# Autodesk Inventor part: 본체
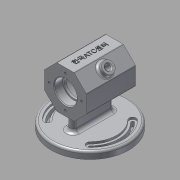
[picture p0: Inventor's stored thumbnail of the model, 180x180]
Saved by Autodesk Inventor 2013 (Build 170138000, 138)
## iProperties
Created: 2017-06
Part Number: 본체
Material: 알루미늄 6061
Document SubType Name: Modeling
Designer: Administrator
Density: 2.71 g/cm^3
Mass: 656.312 g
Surface Area: 514.605 cm^2
Volume: 242.182 cm^3
Author: Administrator
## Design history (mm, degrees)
sketch "스케치2"
  geometry: L1 (0, 0)-(70, 0); L2 (0, 17)-(0, 30); L3 (0, 30)-(70, 30); L4 (70, 17)-(70, 30); L5 (1, 16)-(11.7, 16); L6 (12, 15.7)-(12, 14); L7 (12, 14)-(15, 14); L8 (15, 14)-(15, 22); L9 (18, 25)-(52, 25); L10 (55, 22)-(55, 14); L11 (55, 14)-(58, 14); L12 (58, 14)-(58, 15.7); L13 (58.3, 16)-(69, 16); L14 (0, 17)-(1, 16); L15 (70, 17)-(69, 16); A1 r 3 centre (52, 22) between (55, 22) and (52, 25); A2 r 3 centre (18, 22) between (18, 25) and (15, 22); A3 r 0.3 centre (58.3, 15.7) between (58.3, 16) and (58, 15.7); A4 r 0.3 centre (11.7, 15.7) between (12, 15.7) and (11.7, 16); 8 further points
  constraints: 30 end point, 14 point on line, 8 point on circle, 8 tangent, 6 parallel, 6 perpendicular, 4 centre point, 1 collinear, 1 equal radius, 1 horizontal
  dimensions: "d0" = 70 distance of L1.start L1.end; "d1" = 60 diameter of L3 L1; "d2" = 32 diameter of L5 L1; "d3" = 28 diameter of L7 L1; "d4" = 12 distance from line of point (0, 16) L6; "d5" = 12 distance of point (70, 16) point (58, 16); "d6" = 32 diameter of L13 L1; "d7" = 28 diameter of L11 L1; "d9" = 40 distance between parallel lines of L10 L8; "d10" = 3 radius of A1; "d11" = 1 distance of L2.start point (0, 16); "d12" = 1 distance of L5.start point (0, 16) (= d11); "d13" = 1 distance of L4.start point (70, 16) (= d11); "d14" = 1 distance of L13.end point (70, 16) (= d13); "d15" = 0.3 distance of point (58.3, 16) point (58, 16); "d16" = 0.3 distance of point (58, 15.7) point (58, 16) (= d15); "d17" = 0.3 distance of point (11.7, 16) point (12, 16) (= d15); "d18" = 0.3 distance of point (12, 15.7) point (12, 16) (= d17); "d148" = 50 diameter of L9 L1; "d160" = 0.3 radius of A3; "d161" = 0.3 radius of A4
revolve "회전1" sketch "스케치2" stored, may be unused: angle "d19" = 90 deg
sketch "스케치7"
  geometry: L1 (0, 0)-(0, 30); L2 (0, 30)-(12.426, 30); L3 (6.506, 15.706)-(12.426, 30); L4 (-6.506, 15.706)-(-12.426, 30); L5 (0, 30)-(-12.426, 30); A1 r 17 centre (0, 0) between (-7.11, 15.442) and (10.381, 13.462) reference; A2 r 17 centre (0, 0) between (10.381, 13.462) and (-7.11, 15.442); A3 r 17 centre (0, 0) between (6.506, 15.706) and (-6.506, 15.706); 1 further point
  constraints: 10 end point, 7 point on circle, 2 centre point, 2 symmetric about line, 1 horizontal, 1 perpendicular, 1 vertical, 1 vertical alignment, 1 other
  dimensions: "d43" = 22.5 deg angle of L3 L1
extrude "돌출3" join sketch "스케치7" distance "d44" = 70; taper "d45" = 0 deg
node "작업 평면1"
sketch "스케치8"
  geometry: C1 r 55 at (0, 35); 1 further point
  constraints: 1 centre point
  dimensions: "d50" = 0 horizontal distance of point (0, 0) C1.centre; "d51" = 35 distance of C1.centre point (0, 0); "d52" = 110 diameter of C1
extrude "돌출4" join sketch "스케치8" distance "d53" = 10; taper "d54" = 0 deg
sketch "스케치9"
  geometry: L1 (0, -24)-(0, 24); L2 (-5, -24)-(-5, 24); L3 (4.951, 24.701)-(4.951, -24.701); C1 r 55 at (0, 0) reference; A1 r 5 centre (0, -24) between (-5, -24) and (4.951, -24.701); A2 r 5 centre (0, 24) between (-5, 24) and (4.951, 24.701); 1 further point
  constraints: 6 end point, 4 point on circle, 2 centre point, 2 coincident, 1 equal radius, 1 parallel, 1 tangent, 1 vertical
  dimensions: "d56" = 0 distance from line of C1.centre L1; "d57" = 48 distance of L1.start L1.end; "d58" = 24 distance of L1.start C1.centre; "d59" = 10 diameter of A1
extrude "돌출5" join sketch "스케치9" stored distance "d60" = 10; taper "d61" = 0 deg
sketch "스케치10"
  geometry: L1 (-5, -24)-(-5, 24) reference; L2 (4.951, 24.701)-(4.951, -24.701) reference; L3 (0, 0)-(-48, 0); L4 (0, 0)-(48, 0); L5 (0, -24)-(0, 24); L6 (0, 0)-(-5, -5); L7 (-26.87, -26.87)-(-33.941, -33.941); L8 (0, 0)-(-5, 5); L9 (-26.87, 26.87)-(-33.941, 33.941); L10 (0, 0)-(4.951, -4.951); L11 (26.87, -26.87)-(33.941, -33.941); L12 (0, 0)-(4.951, 4.951); L13 (26.87, 26.87)-(33.941, 33.941); C1 r 55 at (0, 0) reference; A1 r 5 centre (0, 24) between (4.951, 24.701) and (-5, 24) reference; A2 r 5 centre (0, -24) between (-5, -24) and (4.951, -24.701) reference; A3 r 5 centre (-30.406, -30.406) between (-33.941, -33.941) and (-26.67, -33.73); A4 r 5 centre (-30.406, 30.406) between (-26.87, 26.87) and (-26.67, 33.73); A5 r 5 centre (30.406, -30.406) between (33.941, -33.941) and (26.67, -33.73); A6 r 5 centre (30.406, 30.406) between (26.87, 26.87) and (26.67, 33.73); A7 r 38 centre (0, 0) between (26.87, -26.87) and (26.87, 26.87); A8 r 38 centre (0, 0) between (-26.87, 26.87) and (-26.87, -26.87); A9 r 43 centre (0, 0) between (26.67, -33.73) and (26.67, 33.73); A10 r 43 centre (0, 0) between (-26.67, 33.73) and (-26.67, -33.73); A11 r 48 centre (0, 0) between (33.941, -33.941) and (33.941, 33.941); A12 r 48 centre (0, 0) between (-33.941, 33.941) and (-33.941, -33.941); 1 further point
  constraints: 30 point on circle, 22 end point, 10 centre point, 4 midpoint, 4 point on line, 3 coincident, 3 symmetric about line, 2 perpendicular, 1 collinear
  dimensions: "d67" = 45 deg angle of L3 L7
extrude "돌출6" cut sketch "스케치10" distance "d68" = 3; taper "d69" = 0 deg
node "작업 평면2"
sketch "스케치11"
  geometry: C1 r 8 at (12.426, 35); 1 further point
  constraints: 1 centre point
  dimensions: "d71" = 0 horizontal distance of point (12.426, 0) C1.centre; "d72" = 35 distance of point (12.426, 0) C1.centre; "d73" = 16 diameter of C1
extrude "돌출7" join sketch "스케치11" stored distance "d74" = 10; taper "d75" = 0 deg
sketch "스케치12"
  geometry: C1 r 8 at (0, 0) reference; C2 r 4 at (0, 0); 1 further point
  constraints: 1 centre point, 1 coincident
  dimensions: "d76" = 8 diameter of C2
extrude "돌출8" cut sketch "스케치12" stored distance "d78" = 10; taper "d79" = 0 deg
fillet "모깎기1" dims "d80" = 3, "d84" = 5
sketch "스케치16" dims "d112" = 46
  geometry: C1 r 17 at (12.426, 30) reference; 2 further points
  constraints: 1 coincident, 1 vertical alignment, 2 other
  dimensions: "d114" = 0 horizontal distance of point (12.426, 53) point (12.426, 30)
hole "구멍3" sketch "스케치16" at (12.426, 53) diameter "d115" = 3.242; stored, may be unused: countersink angle "d119" = 90 deg, drill point angle "d121" = 118 deg; dims "d116" = 8, "d117" = 4, "d118" = 2, "d120" = 10
sketch "스케치17" dims "d127" = 46
  geometry: C1 r 17 at (12.426, 30) reference; 2 further points
  constraints: 1 coincident, 1 vertical alignment, 2 other
  dimensions: "d125" = 0 horizontal distance of point (12.426, 30) point (12.426, 7)
hole "구멍4" sketch "스케치17" at (12.426, 7) diameter "d128" = 3.242; stored, may be unused: countersink angle "d132" = 90 deg, drill point angle "d134" = 118 deg; dims "d129" = 8, "d130" = 4, "d131" = 2, "d133" = 10
sketch "스케치18"
  geometry: L1 (24.853, 0)-(0, 0) reference; L2 (4.194, 2.871)-(4.194, 67.129); L3 (4.194, 67.129)-(20.659, 67.129); L4 (20.659, 67.129)-(20.659, 2.871); L5 (20.659, 2.871)-(4.194, 2.871); L6 (4.194, 35)-(20.659, 35); L7 (12.426, 2.871)-(12.426, 67.129); L8 (-17.574, 0)-(-17.574, 70) reference; 1 further point
  constraints: 4 end point, 4 midpoint, 2 other
  dimensions: "d138" = 30 distance between parallel lines of L8 L7; "d139" = 35 distance between parallel lines of L6 L1
feature "엠보싱1" sketch "스케치18" dims "d0" = 70, "d1" = 60, "d2" = 32, "d3" = 28, "d4" = 12, "d5" = 12, "d6" = 32, "d7" = 28, "d9" = 40, "d10" = 3, "d11" = 1, "d12" = 1 (= d11), "d13" = 1 (= d11), "d14" = 1 (= d13), "d15" = 0.3, "d16" = 0.3 (= d15), "d17" = 0.3 (= d15), "d18" = 0.3 (= d17), "d140" = 0.5, "d141" = 0, "d148" = 50, "d160" = 0.3, "d161" = 0.3
sketch "스케치20"
  geometry: A1 r 5 centre (-30.406, -30.406) between (-33.941, -33.941) and (-26.87, -26.87) reference; A2 r 5 centre (-30.406, 30.406) between (-26.87, 26.87) and (-33.941, 33.941) reference; A3 r 48 centre (0, 0) between (33.941, -33.941) and (33.941, 33.941) reference; A4 r 5 centre (30.406, 30.406) between (33.941, 33.941) and (26.87, 26.87) reference; A5 r 38 centre (0, 0) between (26.87, -26.87) and (26.87, 26.87) reference; A6 r 5 centre (30.406, -30.406) between (26.87, -26.87) and (33.941, -33.941) reference; A7 r 2 centre (-30.406, -30.406) between (-31.82, -31.82) and (-28.959, -31.787); A8 r 2 centre (-30.406, 30.406) between (-31.82, 31.82) and (-28.959, 31.787); A9 r 2 centre (30.406, -30.406) between (28.991, -28.991) and (28.959, -31.787); A10 r 2 centre (30.406, 30.406) between (28.991, 28.991) and (28.959, 31.787); A11 r 41 centre (0, 0) between (28.991, -28.991) and (28.991, 28.991); A12 r 41 centre (0, 0) between (-28.991, 28.991) and (-28.991, -28.991); A13 r 43 centre (0, 0) between (28.959, -31.787) and (28.959, 31.787); A14 r 43 centre (0, 0) between (-28.959, 31.787) and (-28.959, -31.787); A15 r 45 centre (0, 0) between (31.82, -31.82) and (31.82, 31.82); A16 r 45 centre (0, 0) between (-31.82, 31.82) and (-31.82, -31.82); 1 further point
  constraints: 25 point on circle, 10 centre point, 5 coincident, 3 equal radius
  dimensions: "d142" = 4 diameter of A7
extrude "돌출9" cut sketch "스케치20" distance "d146" = 7; taper "d147" = 0 deg
node "작업 평면3"
sketch "스케치22"
  geometry: C1 r 25 at (12.426, 30); 1 further point
  constraints: 1 centre point, 1 coincident
  dimensions: "d149" = 50 diameter of C1
extrude "돌출10" cut sketch "스케치22" stored distance "d151" = 40; taper "d152" = 0 deg
chamfer "모따기2" distance "d153" = 1; stored, may be unused: second distance "d154" = 2, angle "d155" = 45 deg
fillet "모깎기2" dims "d159" = 1
fillet "모깎기3" dims "d162" = 3
node "솔리드1"
pattern_circular "원형 패턴1" dims angle "d47" = 360 deg
pattern_circular "원형 패턴4" dims angle "d123" = 360 deg
pattern_circular "원형 패턴5" dims angle "d136" = 360 deg
node "투영된 루프4"
other parameters: "d49" = -62, "d62" = 86, "d64" = 76, "d65" = 96, "d66" = 45 deg, "d70" = 7, "d144" = 2, "d145" = 2
